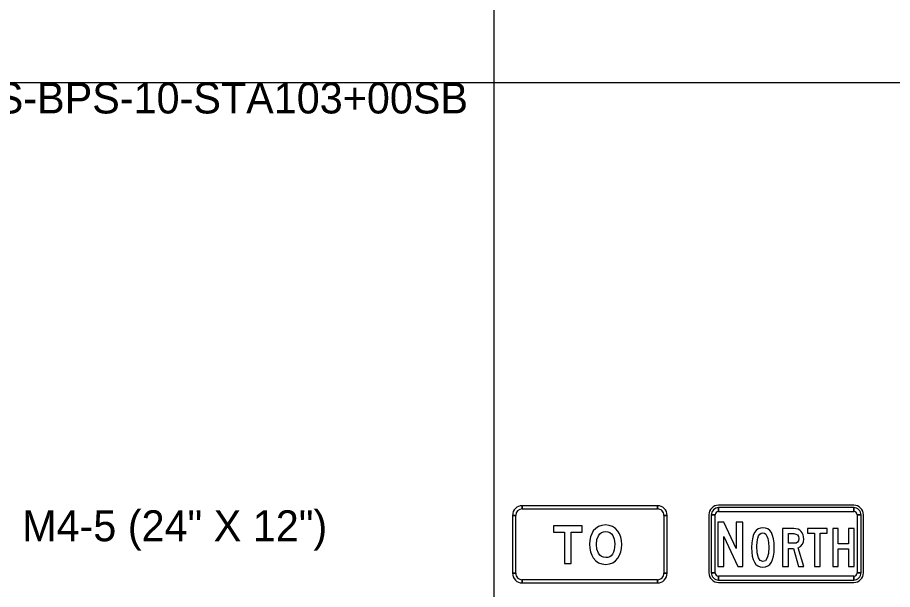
# Model space of a CAD drawing. Extents: x 1001568 to 1002149, y 1840825 to 1841423.
# Drawn here: x 1001914.49 to 1001925.81, y 1841278.91 to 1841286.31 of the extents above; entities that cross this region are included whole.
import ezdxf

# ---------------------------------------------------------------- set-up
doc = ezdxf.new("R2010")
doc.units = 0
for name, color, linetype in [('40', 7, 'Continuous'), ('R_No Plot', 7, 'Continuous'), ('SIGNS', 7, 'Continuous')]:
    doc.layers.add(name, color=color, linetype=linetype)

msp = doc.modelspace()

# ---------------------------------------------------------------- linework, layer by layer
at = {"layer": 'R_No Plot'}
for p, q in [((1001920.65, 1841310.667), (1001920.65, 1841248.127)), ((1001890.65, 1841285.469), (1001982.133, 1841285.469))]:
    msp.add_line(p, q, dxfattribs=at)
at = {"layer": 'SIGNS'}
for p, q in [((1001922.767, 1841279.994), (1001921.017, 1841279.994)), ((1001921.017, 1841279.952), (1001921.017, 1841279.994)), ((1001922.767, 1841279.994), (1001922.767, 1841279.952)), ((1001925.307, 1841280), (1001923.557, 1841280)), ((1001923.557, 1841279.917), (1001923.557, 1841279.969)), ((1001925.307, 1841279.969), (1001925.307, 1841279.917)), ((1001920.892, 1841279.869), (1001920.892, 1841279.119)), ((1001920.892, 1841279.869), (1001920.934, 1841279.869)), ((1001922.85, 1841279.869), (1001922.892, 1841279.869)), ((1001922.892, 1841279.119), (1001922.892, 1841279.869)), ((1001923.432, 1841279.875), (1001923.432, 1841279.125)), ((1001923.463, 1841279.875), (1001923.515, 1841279.875)), ((1001925.349, 1841279.875), (1001925.401, 1841279.875)), ((1001925.432, 1841279.125), (1001925.432, 1841279.875)), ((1001920.934, 1841279.119), (1001920.892, 1841279.119)), ((1001922.892, 1841279.119), (1001922.85, 1841279.119)), ((1001923.515, 1841279.125), (1001923.463, 1841279.125)), ((1001923.557, 1841279.031), (1001923.557, 1841279.084)), ((1001925.307, 1841279.084), (1001925.307, 1841279.031)), ((1001925.401, 1841279.125), (1001925.349, 1841279.125)), ((1001921.017, 1841278.994), (1001921.017, 1841279.036)), ((1001921.017, 1841278.994), (1001922.767, 1841278.994)), ((1001922.767, 1841279.036), (1001922.767, 1841278.994)), ((1001923.557, 1841279), (1001925.307, 1841279))]:
    msp.add_line(p, q, dxfattribs=at)
for points in [[(1001922.767, 1841279.994), (1001921.017, 1841279.994), (1001921.017, 1841279.952), (1001922.767, 1841279.952), (1001922.767, 1841279.994), (1001922.767, 1841279.994)], [(1001925.307, 1841279.969), (1001923.557, 1841279.969), (1001923.557, 1841279.917), (1001925.307, 1841279.917), (1001925.307, 1841279.969), (1001925.307, 1841279.969)], [(1001920.892, 1841279.869), (1001920.892, 1841279.119), (1001920.934, 1841279.119), (1001920.934, 1841279.869), (1001920.892, 1841279.869), (1001920.892, 1841279.869)], [(1001922.892, 1841279.119), (1001922.892, 1841279.869), (1001922.85, 1841279.869), (1001922.85, 1841279.119), (1001922.892, 1841279.119), (1001922.892, 1841279.119)], [(1001923.463, 1841279.875), (1001923.463, 1841279.125), (1001923.515, 1841279.125), (1001923.515, 1841279.875), (1001923.463, 1841279.875), (1001923.463, 1841279.875)], [(1001925.401, 1841279.125), (1001925.401, 1841279.875), (1001925.349, 1841279.875), (1001925.349, 1841279.125), (1001925.401, 1841279.125), (1001925.401, 1841279.125)], [(1001923.547, 1841279.209), (1001923.626, 1841279.209), (1001923.626, 1841279.595), (1001923.806, 1841279.209), (1001923.87, 1841279.209), (1001923.87, 1841279.781), (1001923.783, 1841279.781), (1001923.783, 1841279.439), (1001923.626, 1841279.781), (1001923.547, 1841279.781)], [(1001921.564, 1841279.244), (1001921.651, 1841279.244), (1001921.651, 1841279.652), (1001921.794, 1841279.652), (1001921.794, 1841279.734), (1001921.423, 1841279.734), (1001921.423, 1841279.652), (1001921.564, 1841279.652)], [(1001924.799, 1841279.209), (1001924.87, 1841279.209), (1001924.87, 1841279.637), (1001924.962, 1841279.637), (1001924.962, 1841279.699), (1001924.71, 1841279.699), (1001924.71, 1841279.637), (1001924.799, 1841279.637)], [(1001925.037, 1841279.209), (1001925.104, 1841279.209), (1001925.104, 1841279.434), (1001925.238, 1841279.434), (1001925.238, 1841279.209), (1001925.313, 1841279.209), (1001925.313, 1841279.699), (1001925.238, 1841279.699), (1001925.238, 1841279.502), (1001925.104, 1841279.502), (1001925.104, 1841279.699), (1001925.037, 1841279.699)], [(1001923.557, 1841279.031), (1001925.307, 1841279.031), (1001925.307, 1841279.084), (1001923.557, 1841279.084), (1001923.557, 1841279.031), (1001923.557, 1841279.031)], [(1001921.017, 1841278.994), (1001922.767, 1841278.994), (1001922.767, 1841279.036), (1001921.017, 1841279.036), (1001921.017, 1841278.994), (1001921.017, 1841278.994)]]:
    msp.add_lwpolyline(points, close=True, dxfattribs=at)
for points in [[(1001922.304, 1841279.493), (1001922.301, 1841279.543), (1001922.291, 1841279.588), (1001922.275, 1841279.629), (1001922.253, 1841279.666), (1001922.222, 1841279.7), (1001922.185, 1841279.725), (1001922.142, 1841279.739), (1001922.094, 1841279.744), (1001922.046, 1841279.739), (1001922.004, 1841279.725), (1001921.968, 1841279.7), (1001921.937, 1841279.667), (1001921.916, 1841279.631), (1001921.901, 1841279.59), (1001921.892, 1841279.545), (1001921.889, 1841279.495), (1001921.892, 1841279.444), (1001921.901, 1841279.398), (1001921.916, 1841279.355), (1001921.937, 1841279.317), (1001921.969, 1841279.281), (1001922.006, 1841279.255), (1001922.049, 1841279.24), (1001922.098, 1841279.235), (1001922.146, 1841279.24), (1001922.188, 1841279.255), (1001922.225, 1841279.28), (1001922.256, 1841279.316), (1001922.277, 1841279.354), (1001922.292, 1841279.396), (1001922.301, 1841279.442), (1001922.304, 1841279.493)], [(1001922.215, 1841279.5), (1001922.213, 1841279.458), (1001922.207, 1841279.422), (1001922.198, 1841279.392), (1001922.186, 1841279.367), (1001922.169, 1841279.347), (1001922.149, 1841279.334), (1001922.125, 1841279.325), (1001922.098, 1841279.323), (1001922.067, 1841279.326), (1001922.041, 1841279.337), (1001922.02, 1841279.354), (1001922.002, 1841279.379), (1001921.984, 1841279.43), (1001921.977, 1841279.493), (1001921.984, 1841279.555), (1001922.003, 1841279.605), (1001922.02, 1841279.629), (1001922.042, 1841279.646), (1001922.068, 1841279.656), (1001922.098, 1841279.659), (1001922.126, 1841279.656), (1001922.151, 1841279.646), (1001922.172, 1841279.63), (1001922.189, 1841279.607), (1001922.208, 1841279.559), (1001922.215, 1841279.5)], [(1001924.277, 1841279.454), (1001924.275, 1841279.514), (1001924.268, 1841279.565), (1001924.257, 1841279.609), (1001924.241, 1841279.645), (1001924.22, 1841279.673), (1001924.196, 1841279.693), (1001924.166, 1841279.704), (1001924.132, 1841279.709), (1001924.098, 1841279.704), (1001924.068, 1841279.693), (1001924.043, 1841279.673), (1001924.022, 1841279.645), (1001924.006, 1841279.609), (1001923.995, 1841279.565), (1001923.988, 1841279.514), (1001923.985, 1841279.454), (1001923.987, 1841279.394), (1001923.994, 1841279.342), (1001924.005, 1841279.298), (1001924.021, 1841279.263), (1001924.041, 1841279.235), (1001924.066, 1841279.215), (1001924.095, 1841279.203), (1001924.129, 1841279.199), (1001924.164, 1841279.203), (1001924.194, 1841279.215), (1001924.219, 1841279.235), (1001924.24, 1841279.263), (1001924.256, 1841279.298), (1001924.268, 1841279.342), (1001924.275, 1841279.394), (1001924.277, 1841279.454)], [(1001924.207, 1841279.457), (1001924.202, 1841279.375), (1001924.187, 1841279.317), (1001924.163, 1841279.282), (1001924.13, 1841279.27), (1001924.096, 1841279.283), (1001924.072, 1841279.32), (1001924.057, 1841279.382), (1001924.053, 1841279.469), (1001924.056, 1841279.527), (1001924.065, 1841279.575), (1001924.076, 1841279.604), (1001924.091, 1841279.626), (1001924.109, 1841279.638), (1001924.13, 1841279.643), (1001924.151, 1841279.638), (1001924.169, 1841279.624), (1001924.183, 1841279.601), (1001924.195, 1841279.568), (1001924.204, 1841279.518), (1001924.207, 1841279.457)], [(1001924.383, 1841279.209), (1001924.46, 1841279.209), (1001924.46, 1841279.442), (1001924.526, 1841279.442), (1001924.59, 1841279.209), (1001924.66, 1841279.209), (1001924.589, 1841279.45), (1001924.619, 1841279.467), (1001924.642, 1841279.494), (1001924.656, 1841279.526), (1001924.66, 1841279.562), (1001924.658, 1841279.591), (1001924.652, 1841279.617), (1001924.641, 1841279.641), (1001924.627, 1841279.661), (1001924.608, 1841279.677), (1001924.585, 1841279.689), (1001924.559, 1841279.696), (1001924.53, 1841279.699), (1001924.383, 1841279.699), (1001924.383, 1841279.209)], [(1001924.46, 1841279.507), (1001924.46, 1841279.632), (1001924.532, 1841279.632), (1001924.557, 1841279.627), (1001924.577, 1841279.615), (1001924.59, 1841279.595), (1001924.595, 1841279.569), (1001924.591, 1841279.541), (1001924.58, 1841279.522), (1001924.561, 1841279.51), (1001924.534, 1841279.507), (1001924.46, 1841279.507)]]:
    msp.add_lwpolyline(points, dxfattribs=at)
for centre, radius, start, end in [((1001921.017, 1841279.869), 0.125, 90.0002, 179.9998), ((1001921.017, 1841279.869), 0.125, 90.0002, 179.9998), ((1001922.767, 1841279.869), 0.125, 0, 90.0002), ((1001922.767, 1841279.869), 0.125, 0, 90.0002), ((1001923.557, 1841279.875), 0.125, 90.0002, 179.9998), ((1001923.557, 1841279.875), 0.0937, 90.0002, 179.9998), ((1001925.307, 1841279.875), 0.125, 0, 90.0002), ((1001925.307, 1841279.875), 0.0937, 0, 90.0002), ((1001921.017, 1841279.869), 0.0833, 90.0002, 179.9998), ((1001922.767, 1841279.869), 0.0833, 0, 90.0002), ((1001923.557, 1841279.875), 0.0417, 90.0002, 179.9998), ((1001925.307, 1841279.875), 0.0417, 0, 90.0002), ((1001921.017, 1841279.119), 0.125, 179.9998, 270.0001), ((1001921.017, 1841279.119), 0.125, 179.9998, 270.0001), ((1001921.017, 1841279.119), 0.0833, 179.9998, 270.0001), ((1001922.767, 1841279.119), 0.125, 270.0001, 0.0003), ((1001922.767, 1841279.119), 0.125, 270.0001, 0.0003), ((1001922.767, 1841279.119), 0.0833, 270.0001, 0.0003), ((1001923.557, 1841279.125), 0.125, 179.9998, 270.0001), ((1001923.557, 1841279.125), 0.0937, 179.9998, 270.0001), ((1001923.557, 1841279.125), 0.0417, 179.9998, 270.0001), ((1001925.307, 1841279.125), 0.125, 270.0001, 0.0003), ((1001925.307, 1841279.125), 0.0937, 270.0001, 0.0003), ((1001925.307, 1841279.125), 0.0417, 270.0001, 0.0003)]:
    msp.add_arc(centre, radius, start, end, dxfattribs=at)

# ---------------------------------------------------------------- texts
at = {"layer": '40'}
for s, p in [('SS-BPS-10-STA103+00SB', (1001913.849, 1841285.069)), ('M4-5 (24" X 12")', (1001914.547, 1841279.534))]:
    msp.add_text(s, height=0.4, rotation=0, dxfattribs=at).set_placement(p)

doc.saveas('drawing.dxf')
